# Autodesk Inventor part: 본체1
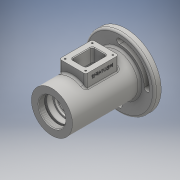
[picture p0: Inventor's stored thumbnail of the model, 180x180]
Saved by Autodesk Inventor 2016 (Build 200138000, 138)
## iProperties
Created: 2017-05
Part Number: 본체1
Material: 일반
Document SubType Name: Modeling
Designer: USER
Density: 1 g/cm^3
Appearance: 기본값
Author: USER
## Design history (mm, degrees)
sketch "스케치1"
  geometry: L1 (0, 0)-(-19.565, 0); L2 (0, 0)-(0, 31); L3 (0, 31)-(102, 31); L4 (102, 31)-(102, 53); L5 (102, 53)-(112, 53); L6 (112, 53)-(112, 31); L7 (112, 31)-(115, 31); L8 (115, 31)-(115, 0); L9 (115, 0)-(0, 0)
  constraints: 18 end point, 6 perpendicular, 2 point on line, 1 horizontal, 1 vertical
  dimensions: "d0" = 62 diameter of L3 L1; "d1" = 106 diameter of L5 L1; "d2" = 13 distance between parallel lines of L8 L4; "d3" = 3 distance of L6.end L7.end; "d4" = 115 distance between parallel lines of L2 L8
revolve "회전1" sketch "스케치1" stored, may be unused: angle "d5" = 90 deg
sketch "스케치3"
  geometry: 2 further points
  constraints: 1 coincident
hole "구멍1" sketch "스케치3" at (0, 0) diameter "d6" = 40.376; stored, may be unused: countersink angle "d10" = 90 deg, drill point angle "d12" = 118 deg; dims "d7" = 9, "d8" = 4, "d9" = 2, "d11" = 9
sketch "스케치4"
  geometry: L1 (9, 20.188)-(9, -20.188) reference; L2 (9, 0)-(9, 24); L3 (9, 24)-(12, 24); L4 (12, 24)-(12, 20); L5 (12, 20)-(21, 20); L6 (21, 20)-(21, 17.5); L7 (21, 17.5)-(24.25, 17.5); L8 (24.25, 17.5)-(24.25, 18.5); L9 (24.25, 18.5)-(26, 18.5); L10 (26, 18.5)-(26, 17.5); L11 (26, 17.5)-(37, 17.5); L12 (37, 17.5)-(37, 26); L13 (37, 26)-(75, 26); L14 (75, 26)-(75, 17.5); L15 (75, 17.5)-(86, 17.5); L16 (86, 17.5)-(86, 16.5); L17 (86, 16.5)-(91, 16.5); L18 (91, 16.5)-(91, 10); L19 (91, 10)-(93.7, 10); L20 (93.7, 10)-(93.7, 12.5); L21 (93.7, 12.5)-(100.3, 12.5); L22 (100.3, 12.5)-(101, 12.904); L23 (101, 12.904)-(101, 16); L24 (101, 16)-(115, 22); L25 (0, 0)-(-21.161, 0); L26 (0, -20.188)-(0, 20.188) reference; L27 (0, -31)-(0, 31) reference; L28 (115, 22)-(115, 0); L29 (115, -31)-(115, 31) reference; L30 (115, 0)-(9, 0)
  constraints: 52 end point, 16 perpendicular, 4 point on line, 3 vertical, 2 midpoint, 1 horizontal
  dimensions: "d13" = 48 diameter of L3 L25; "d14" = 3 distance of L2.end L3.end; "d15" = 40 diameter of L5 L25; "d16" = 35 diameter of L7 L25; "d17" = 21 distance from line of L5.end L26; "d18" = 26 distance between parallel lines of L26 L10; "d19" = 11 distance of L10.end L11.end; "d20" = 38 distance of L12.end L13.end; "d21" = 52 diameter of L13 L25; "d22" = 44 diameter of L24.end L25; "d23" = 32 diameter of L23.end L25; "d24" = 14 horizontal distance of L24.end L23.end; "d25" = 30 deg angle of L21 L22; "d26" = 33 diameter of L17 L25; "d27" = 115 distance from line of L27 L24.end; "d28" = 24 distance from line of L24.end L18; "d29" = 0.7 horizontal distance of L21.end L22.end; "d30" = 25 diameter of L21 L25; "d31" = 20 diameter of L19 L25; "d32" = 2.7 distance of L18.end L19.end; "d33" = 37 diameter of L9 L25; "d34" = 1.75 distance of L8.end L9.end; "d35" = 11 distance of L14.end L15.end
revolve "회전2" sketch "스케치4" stored, may be unused: angle "d36" = 90 deg
node "작업 평면1"
sketch "스케치5"
  geometry: L1 (20, 81)-(-20, 81); L2 (-20, 81)-(-20, 31); L3 (-20, 31)-(20, 31); L4 (20, 31)-(20, 81); L5 (20, 81)-(-20, 31); L6 (-20, 81)-(20, 31); 3 further points
  constraints: 12 end point, 3 midpoint, 2 parallel, 1 horizontal, 1 perpendicular, 1 vertical alignment
  dimensions: "d38" = 50 distance of L1.end L2.end; "d39" = 40 distance of L1.start L1.end; "d40" = 56 distance of point (0, 0) point (0, 56)
extrude "돌출1" join sketch "스케치5" stored distance "d41" = 10; taper "d42" = 0 deg
sketch "스케치6"
  geometry: L1 (11, 40)-(-11, 40); L2 (-11, 40)-(-11, 72); L3 (-11, 72)-(11, 72); L4 (11, 72)-(11, 40); L5 (11, 40)-(-11, 72); L6 (-11, 40)-(11, 72); 3 further points
  constraints: 12 end point, 3 midpoint, 2 parallel, 1 horizontal, 1 perpendicular, 1 vertical alignment
  dimensions: "d43" = 32 distance of L1.end L2.end; "d44" = 22 distance of L1.start L1.end; "d45" = 56 distance of point (0, 0) point (0, 56)
extrude "돌출2" cut sketch "스케치6" stored distance "d46" = 10; taper "d47" = 0 deg
sketch "스케치7"
  geometry: L1 (15.5, 76.5)-(-15.5, 76.5); L2 (-15.5, 76.5)-(-15.5, 35.5); L3 (-15.5, 35.5)-(15.5, 35.5); L4 (15.5, 35.5)-(15.5, 76.5); L5 (15.5, 76.5)-(-15.5, 35.5); L6 (-15.5, 76.5)-(15.5, 35.5); 7 further points
  constraints: 12 end point, 4 coincident, 3 midpoint, 2 parallel, 1 horizontal, 1 perpendicular, 1 vertical alignment
  dimensions: "d48" = 56 distance of point (0, 0) point (0, 56); "d49" = 41 distance of L1.end L2.end; "d50" = 31 distance of L2.end L3.end
hole "구멍2" sketch "스케치7" at (-15.5, 35.5), (-15.5, 76.5), (15.5, 76.5), (15.5, 35.5) diameter "d51" = 2.459; stored, may be unused: countersink angle "d55" = 90 deg, drill point angle "d57" = 118 deg; dims "d52" = 6, "d53" = 4, "d54" = 2, "d56" = 8
sketch "스케치8"
  geometry: L1 (75, -31)-(13, -31) reference; L2 (0, 0)-(0, 50) reference; 2 further points
  constraints: 1 other
  dimensions: "d58" = 56 distance from line of L1 point (8, 25); "d59" = 8 distance from line of point (8, 25) L2
feature "엠보싱1" sketch "스케치8" dims "d60" = 0.5, "d61" = 0
sketch "스케치9"
  geometry: A1 r 41.5 centre (0, 0) between (0, -41.5) and (41.5, 0); A2 r 45.5 centre (0, 0) between (0, -45.5) and (45.5, 0); A3 r 37.5 centre (0, 0) between (0, -37.5) and (37.5, 0); A4 r 4 centre (0, -41.5) between (0, -37.5) and (0, -45.5); A5 r 4 centre (41.5, 0) between (45.5, 0) and (37.5, 0); A6 r 41.5 centre (0, 0) between (0, 41.5) and (-41.5, 0); A7 r 45.5 centre (0, 0) between (0, 45.5) and (-45.5, 0); A8 r 37.5 centre (0, 0) between (0, 37.5) and (-37.5, 0); A9 r 4 centre (0, 41.5) between (0, 37.5) and (0, 45.5); A10 r 4 centre (-41.5, 0) between (-45.5, 0) and (-37.5, 0); 1 further point
  constraints: 20 point on circle, 10 centre point, 8 tangent, 2 coincident, 2 horizontal alignment, 2 vertical alignment
  dimensions: "d62" = 4 radius of A4; "d63" = 4 radius of A10; "d65" = 83 diameter of A1; "d66" = 83 diameter of A6
extrude "돌출3" cut sketch "스케치9" distance "d67" = 17.25; taper "d68" = 0 deg
fillet "모깎기1" dims "d69" = 3
fillet "모깎기2" dims "d70" = 0.3
fillet "모깎기3" dims "d71" = 0.3
chamfer "모따기1" distance "d72" = 1; stored, may be unused: second distance "d73" = 2, angle "d74" = 45 deg
fillet "모깎기4" dims "d75" = 3
fillet "모깎기5" dims "d76" = 3
fillet "모깎기6" dims "d77" = 3
chamfer "모따기2" distance "d78" = 1; stored, may be unused: second distance "d79" = 2, angle "d80" = 45 deg
chamfer "모따기3" distance "d81" = 1; stored, may be unused: second distance "d82" = 2, angle "d83" = 45 deg
fillet "모깎기7" dims "d84" = 3
chamfer "모따기4" distance "d85" = 1; stored, may be unused: second distance "d86" = 2, angle "d87" = 45 deg
node "솔리드1"
other parameters: "d37" = 44
